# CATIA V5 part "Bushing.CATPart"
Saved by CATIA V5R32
Part number: Bushing
Bounding box of the stored display mesh (mm): x -13.45 to 13.45, y 0 to 63, z -13.45 to 13.45
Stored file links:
  D:\PROJECTS\Project 2022\CATIA V5 6R 2022\Resources\Part Files\c14_catia_v5_6r2022_prt\c14-catia-v5-6r2022-figr-14-26 & 27\Part & Asm\Bushing.CATPart
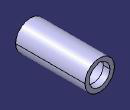
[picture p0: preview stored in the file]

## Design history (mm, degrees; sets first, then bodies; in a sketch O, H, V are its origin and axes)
Body1 (main body)
  Sketch1 on zx-plane, origin (0, 0, 0), H (-1, 0, 0), V (0, 0, 1)
    circle A1 centre (0, 0) radius 9.5
    circle A2 centre (0, 0) radius 13.45
    radius A1 = 9.5
    radius A2 = 13.45
  Pad1: profile Sketch1, direction (0, 1, 0), length 63
  Sketch2 on face of Pad1, origin (0, 63, 0), H (-1, 0, 0), V (0, 0, 1)
    line L1 (-1.5, 9.3808) -> (1.5, 9.3808)
    line L2 (1.5, 9.3808) -> (1.5, 10.1808)
    line L3 (1.5, 10.1808) -> (-1.5, 10.1808)
    line L4 (-1.5, 10.1808) -> (-1.5, 9.3808)
    point P2 (1.5, 9.3808)
    reference projected circle E1 centre (0, 0) radius 9.5 from edge of Pad1
    length L3 = 3
    length L2 = 0.8
    distance V L4 = 1.5
    horizontal: L1 H, L3 H
    vertical: L2 V, L4 V
    coincidence: P2 E1
  Pocket1: profile Sketch2, direction (0, -1, 0), through (limit type 6)
  Sketch3 on xy-plane, origin (0, 0, 0), H (1, 0, 0), V (0, 1, 0)
    line L1 (9.5, 57) -> (10.3, 57)
    line L2 (10.3, 57) -> (10.3, 49)
    line L3 (10.3, 49) -> (9.5, 49)
    line L4 (9.5, 49) -> (9.5, 57)
    reference projected line E1 (13.45, 63) -> (-13.45, 63) from edge of Pad1
    length L2 = 8
    length L1 = 0.8
    distance L3 E1 = 14
    distance V L4 = 9.5
    horizontal: L1 H, L3 H
    vertical: L2 V, L4 V
  Groove1: profile Sketch3, axis axis of face of Pad1, angle 360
